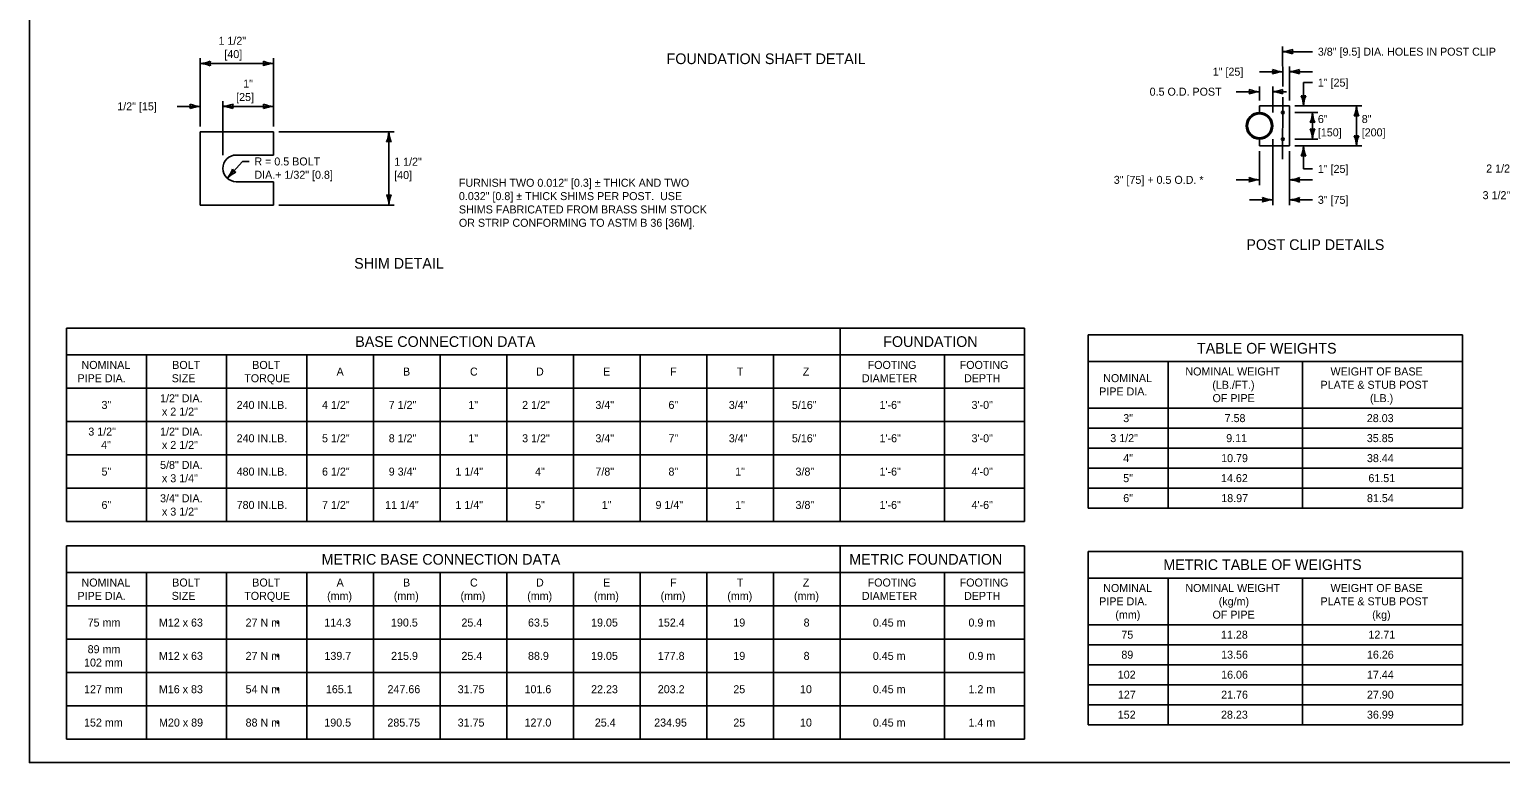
# Model space of a CAD drawing. Extents: x 49991 to 81321, y 49988 to 50028.
# Drawn here: x 49999.38 to 50010.41, y 49987.8 to 49993.3 of the extents above; entities that cross this region are included whole.
import ezdxf

# ---------------------------------------------------------------- set-up
doc = ezdxf.new("R2010")
doc.units = 0
for name, color, linetype in [('Level 1', 7, 'Continuous'), ('Level 2', 7, 'Continuous'), ('Level 3', 7, 'Continuous'), ('Level 5', 7, 'Continuous')]:
    doc.layers.add(name, color=color, linetype=linetype)

msp = doc.modelspace()

# ---------------------------------------------------------------- linework, layer by layer
at = {"layer": 'Level 1'}
for p, q in [((50008.829, 49992.724), (50008.604, 49992.724)), ((50008.604, 49992.674), (50008.604, 49992.724)), ((50008.829, 49992.424), (50008.829, 49992.724)), ((50008.506, 49992.594), (50008.521, 49992.61)), ((50008.511, 49992.612), (50008.565, 49992.666)), ((50008.567, 49992.656), (50008.583, 49992.671)), ((50008.626, 49992.661), (50008.634, 49992.669)), ((50008.636, 49992.658), (50008.644, 49992.665)), ((50008.667, 49992.637), (50008.674, 49992.644)), ((50008.674, 49992.629), (50008.681, 49992.636)), ((50000.664, 49992.53), (50001.214, 49992.53)), ((50000.664, 49992.53), (50000.664, 49991.98)), ((50001.214, 49992.53), (50001.214, 49992.355)), ((50008.508, 49992.543), (50008.516, 49992.551)), ((50008.512, 49992.534), (50008.52, 49992.541)), ((50008.533, 49992.503), (50008.54, 49992.51)), ((50008.541, 49992.496), (50008.548, 49992.503)), ((50008.64, 49992.481), (50008.697, 49992.537)), ((50008.686, 49992.539), (50008.702, 49992.554)), ((50008.691, 49992.593), (50008.7, 49992.602)), ((50008.693, 49992.581), (50008.702, 49992.59)), ((50008.576, 49992.478), (50008.584, 49992.486)), ((50008.587, 49992.475), (50008.596, 49992.484)), ((50008.604, 49992.424), (50008.604, 49992.474)), ((50008.604, 49992.424), (50008.829, 49992.424)), ((50008.623, 49992.476), (50008.639, 49992.491)), ((50000.934, 49992.355), (50001.214, 49992.355)), ((50000.934, 49992.155), (50001.214, 49992.155)), ((50001.214, 49992.155), (50001.214, 49991.98)), ((50000.664, 49991.98), (50001.214, 49991.98))]:
    msp.add_line(p, q, dxfattribs=at)
msp.add_lwpolyline([(49999.384, 49998.999), (50016.75, 49998.999), (50016.75, 49987.799), (49999.384, 49987.799)], close=True, dxfattribs=at)
for centre, radius in [((50008.604, 49992.574), 0.1), ((50008.604, 49992.574), 0.09), ((50008.779, 49992.674), 0.01), ((50008.779, 49992.474), 0.01)]:
    msp.add_circle(centre, radius, dxfattribs=at)
msp.add_arc((50000.934, 49992.255), 0.1, 90, 270, dxfattribs=at)
at = {"layer": 'Level 2'}
for p, q in [((49999.662, 49991.056), (50006.842, 49991.056)), ((49999.662, 49991.056), (49999.662, 49989.606)), ((50005.462, 49991.056), (50005.462, 49989.606)), ((50006.842, 49991.056), (50006.842, 49989.606)), ((50007.321, 49991.007), (50007.321, 49989.707)), ((50007.321, 49991.007), (50010.126, 49991.007)), ((50007.321, 49991.007), (50007.321, 49990.807)), ((50010.126, 49991.007), (50010.126, 49989.707)), ((49999.662, 49990.856), (50006.842, 49990.856)), ((50000.262, 49990.856), (50000.262, 49989.606)), ((50000.862, 49990.856), (50000.862, 49989.606)), ((50001.462, 49990.856), (50001.462, 49989.606)), ((50001.962, 49990.856), (50001.962, 49989.606)), ((50002.462, 49990.856), (50002.462, 49989.606)), ((50002.962, 49990.856), (50002.962, 49989.606)), ((50003.462, 49990.856), (50003.462, 49989.606)), ((50003.962, 49990.856), (50003.962, 49989.606)), ((50004.462, 49990.856), (50004.462, 49989.606)), ((50004.962, 49990.856), (50004.962, 49989.606)), ((50006.242, 49990.856), (50006.242, 49989.606)), ((50007.321, 49990.807), (50010.126, 49990.807)), ((50007.921, 49990.807), (50007.921, 49989.707)), ((50008.928, 49990.807), (50008.928, 49989.707)), ((49999.662, 49990.606), (50006.842, 49990.606)), ((50007.321, 49990.457), (50010.126, 49990.457)), ((49999.662, 49990.356), (50006.842, 49990.356)), ((50007.321, 49990.307), (50010.126, 49990.307)), ((49999.662, 49990.106), (50006.842, 49990.106)), ((50007.321, 49990.157), (50010.126, 49990.157)), ((50007.321, 49990.007), (50010.126, 49990.007)), ((49999.662, 49989.856), (50006.842, 49989.856)), ((50007.321, 49989.857), (50010.126, 49989.857)), ((50007.321, 49989.707), (50010.126, 49989.707)), ((49999.662, 49989.606), (50006.842, 49989.606)), ((49999.662, 49989.424), (50006.842, 49989.424)), ((49999.662, 49989.424), (49999.662, 49987.974)), ((50005.462, 49989.424), (50005.462, 49987.974)), ((50006.842, 49989.424), (50006.842, 49987.974)), ((50007.321, 49989.383), (50007.321, 49988.083)), ((50007.321, 49989.383), (50010.126, 49989.383)), ((50007.321, 49989.383), (50007.321, 49989.183)), ((50010.126, 49989.383), (50010.126, 49988.083)), ((49999.662, 49989.224), (50006.842, 49989.224)), ((50000.262, 49989.224), (50000.262, 49987.974)), ((50000.862, 49989.224), (50000.862, 49987.974)), ((50001.462, 49989.224), (50001.462, 49987.974)), ((50001.962, 49989.224), (50001.962, 49987.974)), ((50002.462, 49989.224), (50002.462, 49987.974)), ((50002.962, 49989.224), (50002.962, 49987.974)), ((50003.462, 49989.224), (50003.462, 49987.974)), ((50003.962, 49989.224), (50003.962, 49987.974)), ((50004.462, 49989.224), (50004.462, 49987.974)), ((50004.962, 49989.224), (50004.962, 49987.974)), ((50006.242, 49989.224), (50006.242, 49987.974)), ((50007.321, 49989.183), (50010.126, 49989.183)), ((50007.921, 49989.183), (50007.921, 49988.083)), ((50008.928, 49989.183), (50008.928, 49988.083)), ((49999.662, 49988.974), (50006.842, 49988.974)), ((50007.321, 49988.833), (50010.126, 49988.833)), ((49999.662, 49988.724), (50006.842, 49988.724)), ((50007.321, 49988.683), (50010.126, 49988.683)), ((50007.321, 49988.533), (50010.126, 49988.533)), ((49999.662, 49988.474), (50006.842, 49988.474)), ((50007.321, 49988.383), (50010.126, 49988.383)), ((49999.662, 49988.224), (50006.842, 49988.224)), ((50007.321, 49988.233), (50010.126, 49988.233)), ((50007.321, 49988.083), (50010.126, 49988.083)), ((49999.662, 49987.974), (50006.842, 49987.974))]:
    msp.add_line(p, q, dxfattribs=at)
for centre in [(50001.246, 49988.849), (50001.246, 49988.599), (50001.246, 49988.349), (50001.246, 49988.099)]:
    msp.add_circle(centre, 0.0054, dxfattribs=at)
at = {"layer": 'Level 3'}
for p, q in [((50000.664, 49992.57), (50000.664, 49993.082)), ((50001.214, 49993.082), (50001.214, 49992.57)), ((50008.778, 49993.13), (50009.002, 49993.13)), ((50000.664, 49993.042), (50001.214, 49993.042)), ((50008.778, 49992.98), (50008.605, 49992.98)), ((50008.829, 49992.764), (50008.829, 49993.02)), ((50009.002, 49992.98), (50008.829, 49992.98)), ((50008.43, 49992.83), (50008.604, 49992.83)), ((50008.604, 49992.764), (50008.604, 49992.87)), ((50008.704, 49992.674), (50008.704, 49992.87)), ((50008.704, 49992.83), (50008.807, 49992.83)), ((50008.934, 49992.724), (50008.934, 49992.898)), ((50008.934, 49992.898), (50009.002, 49992.898)), ((50000.664, 49992.72), (50000.49, 49992.72)), ((50000.834, 49992.76), (50000.834, 49992.355)), ((50000.834, 49992.72), (50001.214, 49992.72)), ((50008.869, 49992.724), (50009.371, 49992.724)), ((50009.331, 49992.424), (50009.331, 49992.724)), ((50008.869, 49992.675), (50009.042, 49992.675)), ((50009.002, 49992.475), (50009.002, 49992.675)), ((50001.254, 49992.53), (50002.118, 49992.53)), ((50002.078, 49992.53), (50002.078, 49991.98)), ((50008.704, 49991.979), (50008.704, 49992.474)), ((50008.869, 49992.475), (50009.042, 49992.475)), ((50008.869, 49992.424), (50009.371, 49992.424)), ((50008.934, 49992.251), (50008.934, 49992.424)), ((50000.98, 49992.307), (50000.867, 49992.18)), ((50000.98, 49992.307), (50001.03, 49992.307)), ((50008.604, 49992.129), (50008.604, 49992.384)), ((50008.829, 49991.979), (50008.829, 49992.384)), ((50008.604, 49992.169), (50008.43, 49992.169)), ((50009.002, 49992.169), (50008.829, 49992.169)), ((50008.934, 49992.251), (50009.002, 49992.251)), ((50001.254, 49991.98), (50002.118, 49991.98)), ((50008.704, 49992.019), (50008.53, 49992.019)), ((50009.002, 49992.019), (50008.829, 49992.019))]:
    msp.add_line(p, q, dxfattribs=at)
for centre, radius, start, end in [((50000.652, 49993.275), 0.233, 272.8273, 292.0772), ((50000.792, 49993.042), 0.0548, 162.1388, 197.8612), ((50001.223, 49993.264), 0.222, 247.456, 267.6395), ((50001.085, 49993.042), 0.0548, 342.1388, 17.8612), ((50008.766, 49993.363), 0.233, 272.8273, 292.0772), ((50008.768, 49992.908), 0.222, 67.456, 87.6395), ((50008.906, 49993.13), 0.0548, 162.1388, 197.8612), ((50000.654, 49992.82), 0.222, 67.456, 87.6395), ((50001.225, 49992.81), 0.233, 92.8273, 112.0772), ((50008.787, 49993.202), 0.222, 247.456, 267.6395), ((50008.65, 49992.98), 0.0548, 342.1388, 17.8612), ((50008.79, 49992.747), 0.233, 92.8273, 112.0772), ((50008.817, 49993.213), 0.233, 272.8273, 292.0772), ((50008.819, 49992.758), 0.222, 67.456, 87.6395), ((50008.957, 49992.98), 0.0548, 162.1388, 197.8612), ((50008.613, 49993.052), 0.222, 247.456, 267.6395), ((50008.475, 49992.83), 0.0548, 342.1388, 17.8612), ((50008.615, 49992.597), 0.233, 92.8273, 112.0772), ((50008.692, 49993.063), 0.233, 272.8273, 292.0772), ((50008.695, 49992.608), 0.222, 67.456, 87.6395), ((50008.832, 49992.83), 0.0548, 162.1388, 197.8612), ((50000.673, 49992.942), 0.222, 247.456, 267.6395), ((50000.535, 49992.72), 0.0548, 342.1388, 17.8612), ((50000.675, 49992.487), 0.233, 92.8273, 112.0772), ((50000.822, 49992.953), 0.233, 272.8273, 292.0772), ((50000.824, 49992.498), 0.222, 67.456, 87.6395), ((50000.962, 49992.72), 0.0548, 162.1388, 197.8612), ((50001.223, 49992.942), 0.222, 247.456, 267.6395), ((50001.085, 49992.72), 0.0548, 342.1388, 17.8612), ((50001.225, 49992.487), 0.233, 92.8273, 112.0772), ((50008.934, 49992.852), 0.0548, 252.1388, 287.8612), ((50008.701, 49992.712), 0.233, 2.8273, 22.0772), ((50009.156, 49992.714), 0.222, 157.456, 177.6395), ((50009.109, 49992.733), 0.222, 337.456, 357.6395), ((50009.564, 49992.735), 0.233, 182.8273, 202.0772), ((50008.78, 49992.684), 0.222, 337.456, 357.6395), ((50009.235, 49992.686), 0.233, 182.8273, 202.0772), ((50009.331, 49992.595), 0.0548, 72.1388, 107.8612), ((50001.856, 49992.539), 0.222, 337.456, 357.6395), ((50002.311, 49992.542), 0.233, 182.8273, 202.0772), ((50009.002, 49992.547), 0.0548, 72.1388, 107.8612), ((50009.002, 49992.603), 0.0548, 252.1388, 287.8612), ((50008.769, 49992.463), 0.233, 2.8273, 22.0772), ((50009.224, 49992.466), 0.222, 157.456, 177.6395), ((50009.331, 49992.552), 0.0548, 252.1388, 287.8612), ((50009.099, 49992.412), 0.233, 2.8273, 22.0772), ((50009.554, 49992.414), 0.222, 157.456, 177.6395), ((50002.078, 49992.402), 0.0548, 72.1388, 107.8612), ((50008.712, 49992.433), 0.222, 337.456, 357.6395), ((50009.167, 49992.435), 0.233, 182.8273, 202.0772), ((50008.934, 49992.295), 0.0548, 72.1388, 107.8612), ((50000.686, 49992.327), 0.233, 321.0173, 340.2671), ((50001.026, 49992.026), 0.222, 115.646, 135.8295), ((50000.952, 49992.276), 0.0548, 210.3288, 246.0511), ((50008.613, 49992.391), 0.222, 247.456, 267.6395), ((50008.475, 49992.169), 0.0548, 342.1388, 17.8612), ((50008.615, 49991.937), 0.233, 92.8273, 112.0772), ((50008.817, 49992.402), 0.233, 272.8273, 292.0772), ((50008.819, 49991.947), 0.222, 67.456, 87.6395), ((50008.957, 49992.169), 0.0548, 162.1388, 197.8612), ((50002.078, 49992.108), 0.0548, 252.1388, 287.8612), ((50001.846, 49991.969), 0.233, 2.8273, 22.0772), ((50002.3, 49991.971), 0.222, 157.456, 177.6395), ((50008.713, 49992.241), 0.222, 247.456, 267.6395), ((50008.575, 49992.019), 0.0548, 342.1388, 17.8612), ((50008.715, 49991.787), 0.233, 92.8273, 112.0772), ((50008.817, 49992.252), 0.233, 272.8273, 292.0772), ((50008.819, 49991.797), 0.222, 67.456, 87.6395), ((50008.957, 49992.019), 0.0548, 162.1388, 197.8612)]:
    msp.add_arc(centre, radius, start, end, dxfattribs=at)
at = {"layer": 'Level 5'}
for p, q in [((50008.779, 49992.87), (50008.777, 49993.17)), ((50008.778, 49992.324), (50008.779, 49992.79))]:
    msp.add_line(p, q, dxfattribs=at)

# ---------------------------------------------------------------- texts
at = {"layer": 'Level 2'}
for s, height, p in [('1 1/2"', 0.06, (50000.801, 49993.182)), ('3/8" [9.5] DIA. HOLES IN POST CLIP', 0.06, (50009.042, 49993.1)), ('[40]', 0.06, (50000.845, 49993.082)), ('FOUNDATION SHAFT DETAIL', 0.08, (50004.16, 49993.037)), ('1" [25]', 0.06, (50008.254, 49992.95)), ('1"', 0.06, (50000.986, 49992.86)), ('0.5 O.D. POST', 0.06, (50007.781, 49992.8)), ('1" [25]', 0.06, (50009.042, 49992.868)), ('1/2" [15]', 0.06, (50000.042, 49992.69)), ('[25]', 0.06, (50000.933, 49992.76)), ('6"', 0.06, (50009.042, 49992.595)), ('8"', 0.06, (50009.371, 49992.595)), ('[150]', 0.06, (50009.042, 49992.495)), ('[200]', 0.06, (50009.371, 49992.495)), ('R = 0.5 BOLT', 0.06, (50001.07, 49992.277)), ('1 1/2"', 0.06, (50002.118, 49992.275)), ('1" [25]', 0.06, (50009.042, 49992.221)), ('2 1/2" [64] DIA. PIPE = 4 7/16" [111.5]', 0.06, (50010.304, 49992.224)), ('DIA.+ 1/32" [0.8]', 0.06, (50001.07, 49992.177)), ('[40]', 0.06, (50002.118, 49992.175)), ('FURNISH TWO 0.012" [0.3] ± THICK AND TWO', 0.06, (50002.603, 49992.117)), ('3" [75] + 0.5 O.D. *', 0.06, (50007.512, 49992.139)), ('0.032" [0.8] ± THICK SHIMS PER POST.  USE', 0.06, (50002.603, 49992.017)), ('3 1/2" [89] DIA. PIPE = 5" [126.0]', 0.06, (50010.277, 49992.024)), ('SHIMS FABRICATED FROM BRASS SHIM STOCK', 0.06, (50002.603, 49991.917)), ('3" [75]', 0.06, (50009.042, 49991.989)), ('OR STRIP CONFORMING TO ASTM B 36 [36M].', 0.06, (50002.603, 49991.817)), ('POST CLIP DETAILS', 0.08, (50008.506, 49991.643)), ('SHIM DETAIL', 0.08, (50001.818, 49991.503)), ('BASE CONNECTION DATA', 0.08, (50001.826, 49990.916)), ('FOUNDATION', 0.08, (50005.784, 49990.916)), ('TABLE OF WEIGHTS', 0.08, (50008.136, 49990.866)), ('NOMINAL', 0.06, (49999.774, 49990.751)), ('BOLT', 0.06, (50000.454, 49990.751)), ('BOLT', 0.06, (50001.054, 49990.751)), ('A', 0.06, (50001.686, 49990.701)), ('B', 0.06, (50002.184, 49990.701)), ('C', 0.06, (50002.686, 49990.701)), ('D', 0.06, (50003.181, 49990.701)), ('E', 0.06, (50003.684, 49990.701)), ('F', 0.06, (50004.186, 49990.701)), ('T', 0.06, (50004.686, 49990.701)), ('Z', 0.06, (50005.181, 49990.701)), ('FOOTING', 0.06, (50005.667, 49990.751)), ('FOOTING', 0.06, (50006.357, 49990.751)), ('NOMINAL WEIGHT', 0.06, (50008.049, 49990.702)), ('WEIGHT OF BASE ', 0.06, (50009.137, 49990.702)), ('PIPE DIA.', 0.06, (49999.744, 49990.651)), ('SIZE', 0.06, (50000.45, 49990.651)), ('TORQUE', 0.06, (50000.994, 49990.651)), ('DIAMETER', 0.06, (50005.624, 49990.651)), ('DEPTH', 0.06, (50006.39, 49990.651)), ('NOMINAL', 0.06, (50007.433, 49990.652)), ('(LB./FT.)', 0.06, (50008.251, 49990.602)), ('PLATE & STUB POST', 0.06, (50009.062, 49990.602)), ('1/2" DIA.', 0.06, (50000.363, 49990.501)), ('4 1/2"', 0.06, (50001.577, 49990.451)), ('7 1/2"', 0.06, (50002.077, 49990.451)), ('2 1/2"', 0.06, (50003.077, 49990.451)), (' 3/4"', 0.06, (50003.604, 49990.451)), (' 3/4"', 0.06, (50004.604, 49990.451)), (' 5/16"', 0.06, (50005.077, 49990.451)), ('PIPE DIA.', 0.06, (50007.403, 49990.552)), (' OF PIPE', 0.06, (50008.23, 49990.502)), ('(LB.)', 0.06, (50009.433, 49990.502)), ('3"', 0.06, (49999.924, 49990.451)), ('x 2 1/2"', 0.06, (50000.377, 49990.401)), ('240 IN.LB.', 0.06, (50000.937, 49990.451)), ('1"', 0.06, (50002.674, 49990.451)), ('6"', 0.06, (50004.174, 49990.451)), ('1\'-6"', 0.06, (50005.756, 49990.451)), ('3\'-0"', 0.06, (50006.446, 49990.451)), ('3"', 0.06, (50007.583, 49990.352)), ('7.58', 0.06, (50008.343, 49990.352)), ('28.03', 0.06, (50009.409, 49990.352)), ('3 1/2"', 0.06, (49999.825, 49990.251)), ('1/2" DIA.', 0.06, (50000.363, 49990.251)), ('4"', 0.06, (49999.921, 49990.151)), ('x 2 1/2"', 0.06, (50000.377, 49990.151)), ('240 IN.LB.', 0.06, (50000.937, 49990.201)), ('5 1/2"', 0.06, (50001.577, 49990.201)), ('8 1/2"', 0.06, (50002.077, 49990.201)), ('1"', 0.06, (50002.674, 49990.201)), ('3 1/2"', 0.06, (50003.077, 49990.201)), (' 3/4"', 0.06, (50003.604, 49990.201)), ('7"', 0.06, (50004.174, 49990.201)), (' 3/4"', 0.06, (50004.604, 49990.201)), (' 5/16"', 0.06, (50005.077, 49990.201)), ('1\'-6"', 0.06, (50005.756, 49990.201)), ('3\'-0"', 0.06, (50006.446, 49990.201)), ('3 1/2"', 0.06, (50007.486, 49990.202)), ('9.11', 0.06, (50008.355, 49990.202)), ('35.85', 0.06, (50009.409, 49990.202)), ('4"', 0.06, (50007.583, 49990.052)), ('10.79', 0.06, (50008.317, 49990.052)), ('38.44', 0.06, (50009.41, 49990.052)), ('5"', 0.06, (49999.924, 49989.951)), ('5/8" DIA.', 0.06, (50000.363, 49990.001)), ('x 3 1/4"', 0.06, (50000.377, 49989.901)), ('480 IN.LB.', 0.06, (50000.937, 49989.951)), ('6 1/2"', 0.06, (50001.577, 49989.951)), ('9 3/4"', 0.06, (50002.077, 49989.951)), ('1 1/4"', 0.06, (50002.577, 49989.951)), ('4"', 0.06, (50003.174, 49989.951)), (' 7/8"', 0.06, (50003.604, 49989.951)), ('8"', 0.06, (50004.174, 49989.951)), ('1"', 0.06, (50004.674, 49989.951)), (' 3/8"', 0.06, (50005.104, 49989.951)), ('1\'-6"', 0.06, (50005.756, 49989.951)), ('4\'-0"', 0.06, (50006.446, 49989.951)), ('5"', 0.06, (50007.583, 49989.902)), ('14.62', 0.06, (50008.316, 49989.902)), ('61.51', 0.06, (50009.421, 49989.902)), ('6"', 0.06, (49999.924, 49989.701)), ('3/4" DIA.', 0.06, (50000.363, 49989.751)), ('780 IN.LB.', 0.06, (50000.937, 49989.701)), ('7 1/2"', 0.06, (50001.577, 49989.701)), ('11 1/4"', 0.06, (50002.05, 49989.701)), ('1 1/4"', 0.06, (50002.577, 49989.701)), ('5"', 0.06, (50003.174, 49989.701)), ('1"', 0.06, (50003.674, 49989.701)), ('9 1/4"', 0.06, (50004.077, 49989.701)), ('1"', 0.06, (50004.674, 49989.701)), (' 3/8"', 0.06, (50005.104, 49989.701)), ('1\'-6"', 0.06, (50005.756, 49989.701)), ('4\'-6"', 0.06, (50006.446, 49989.701)), ('6"', 0.06, (50007.583, 49989.752)), ('18.97', 0.06, (50008.318, 49989.752)), ('81.54', 0.06, (50009.41, 49989.752)), ('x 3 1/2"', 0.06, (50000.377, 49989.651)), ('METRIC BASE CONNECTION DATA', 0.08, (50001.574, 49989.283)), ('METRIC FOUNDATION', 0.08, (50005.529, 49989.283)), ('METRIC TABLE OF WEIGHTS', 0.08, (50007.884, 49989.243)), ('PIPE DIA.', 0.06, (49999.744, 49989.019)), ('NOMINAL', 0.06, (49999.774, 49989.119)), ('SIZE', 0.06, (50000.45, 49989.019)), ('BOLT', 0.06, (50000.454, 49989.119)), ('TORQUE', 0.06, (50000.994, 49989.019)), ('BOLT', 0.06, (50001.054, 49989.119)), ('(mm)', 0.06, (50001.615, 49989.019)), ('A', 0.06, (50001.686, 49989.119)), ('(mm)', 0.06, (50002.115, 49989.019)), ('B', 0.06, (50002.184, 49989.119)), ('(mm)', 0.06, (50002.615, 49989.019)), ('C', 0.06, (50002.686, 49989.119)), ('(mm)', 0.06, (50003.115, 49989.019)), ('D', 0.06, (50003.181, 49989.119)), ('(mm)', 0.06, (50003.615, 49989.019)), ('E', 0.06, (50003.684, 49989.119)), ('(mm)', 0.06, (50004.115, 49989.019)), ('F', 0.06, (50004.186, 49989.119)), ('(mm)', 0.06, (50004.615, 49989.019)), ('T', 0.06, (50004.686, 49989.119)), ('(mm)', 0.06, (50005.115, 49989.019)), ('Z', 0.06, (50005.181, 49989.119)), ('DIAMETER', 0.06, (50005.624, 49989.019)), ('FOOTING', 0.06, (50005.667, 49989.119)), ('FOOTING', 0.06, (50006.357, 49989.119)), ('DEPTH', 0.06, (50006.39, 49989.019)), ('NOMINAL', 0.06, (50007.433, 49989.078)), ('NOMINAL WEIGHT', 0.06, (50008.049, 49989.078)), ('WEIGHT OF BASE ', 0.06, (50009.137, 49989.078)), ('PIPE DIA.', 0.06, (50007.403, 49988.978)), ('(kg/m)', 0.06, (50008.299, 49988.978)), ('PLATE & STUB POST', 0.06, (50009.062, 49988.978)), ('75 mm', 0.06, (49999.82, 49988.819)), ('M12 x 63', 0.06, (50000.354, 49988.819)), ('27 N m', 0.06, (50001.004, 49988.819)), ('114.3', 0.06, (50001.594, 49988.819)), ('190.5', 0.06, (50002.094, 49988.819)), ('25.4', 0.06, (50002.622, 49988.819)), ('63.5', 0.06, (50003.121, 49988.819)), ('19.05', 0.06, (50003.594, 49988.819)), ('152.4', 0.06, (50004.095, 49988.819)), ('19', 0.06, (50004.66, 49988.819)), ('8', 0.06, (50005.187, 49988.819)), ('0.45 m', 0.06, (50005.706, 49988.819)), ('0.9 m', 0.06, (50006.423, 49988.819)), ('(mm)', 0.06, (50007.524, 49988.878)), (' OF PIPE', 0.06, (50008.23, 49988.878)), ('(kg)', 0.06, (50009.449, 49988.878)), ('75', 0.06, (50007.569, 49988.728)), ('11.28', 0.06, (50008.316, 49988.728)), ('12.71', 0.06, (50009.421, 49988.728)), ('89 mm', 0.06, (49999.82, 49988.619)), ('89', 0.06, (50007.569, 49988.578)), ('13.56', 0.06, (50008.317, 49988.578)), ('16.26', 0.06, (50009.41, 49988.578)), ('102 mm', 0.06, (49999.793, 49988.519)), ('M12 x 63', 0.06, (50000.354, 49988.569)), ('27 N m', 0.06, (50001.004, 49988.569)), ('139.7', 0.06, (50001.595, 49988.569)), ('215.9', 0.06, (50002.095, 49988.569)), ('25.4', 0.06, (50002.622, 49988.569)), ('88.9', 0.06, (50003.121, 49988.569)), ('19.05', 0.06, (50003.594, 49988.569)), ('177.8', 0.06, (50004.094, 49988.569)), ('19', 0.06, (50004.66, 49988.569)), ('8', 0.06, (50005.187, 49988.569)), ('0.45 m', 0.06, (50005.706, 49988.569)), ('0.9 m', 0.06, (50006.423, 49988.569)), ('102', 0.06, (50007.542, 49988.428)), ('16.06', 0.06, (50008.317, 49988.428)), ('17.44', 0.06, (50009.41, 49988.428)), ('127 mm', 0.06, (49999.793, 49988.319)), ('M16 x 83', 0.06, (50000.354, 49988.319)), ('54 N m', 0.06, (50001.004, 49988.319)), ('165.1', 0.06, (50001.606, 49988.319)), ('247.66', 0.06, (50002.068, 49988.319)), ('31.75', 0.06, (50002.594, 49988.319)), ('101.6', 0.06, (50003.095, 49988.319)), ('22.23', 0.06, (50003.594, 49988.319)), ('203.2', 0.06, (50004.094, 49988.319)), ('25', 0.06, (50004.66, 49988.319)), ('10', 0.06, (50005.16, 49988.319)), ('0.45 m', 0.06, (50005.706, 49988.319)), ('1.2 m', 0.06, (50006.423, 49988.319)), ('127', 0.06, (50007.543, 49988.278)), ('21.76', 0.06, (50008.317, 49988.278)), ('27.90', 0.06, (50009.41, 49988.278)), ('152 mm', 0.06, (49999.793, 49988.069)), ('M20 x 89', 0.06, (50000.355, 49988.069)), ('88 N m', 0.06, (50001.004, 49988.069)), ('190.5', 0.06, (50001.594, 49988.069)), ('285.75', 0.06, (50002.067, 49988.069)), ('31.75', 0.06, (50002.594, 49988.069)), ('127.0', 0.06, (50003.095, 49988.069)), ('25.4', 0.06, (50003.622, 49988.069)), ('234.95', 0.06, (50004.067, 49988.069)), ('25', 0.06, (50004.66, 49988.069)), ('10', 0.06, (50005.16, 49988.069)), ('0.45 m', 0.06, (50005.706, 49988.069)), ('1.4 m', 0.06, (50006.423, 49988.069)), ('152', 0.06, (50007.542, 49988.128)), ('28.23', 0.06, (50008.316, 49988.128)), ('36.99', 0.06, (50009.41, 49988.128))]:
    msp.add_text(s, height=height, dxfattribs=at).set_placement(p)

doc.saveas('drawing.dxf')
